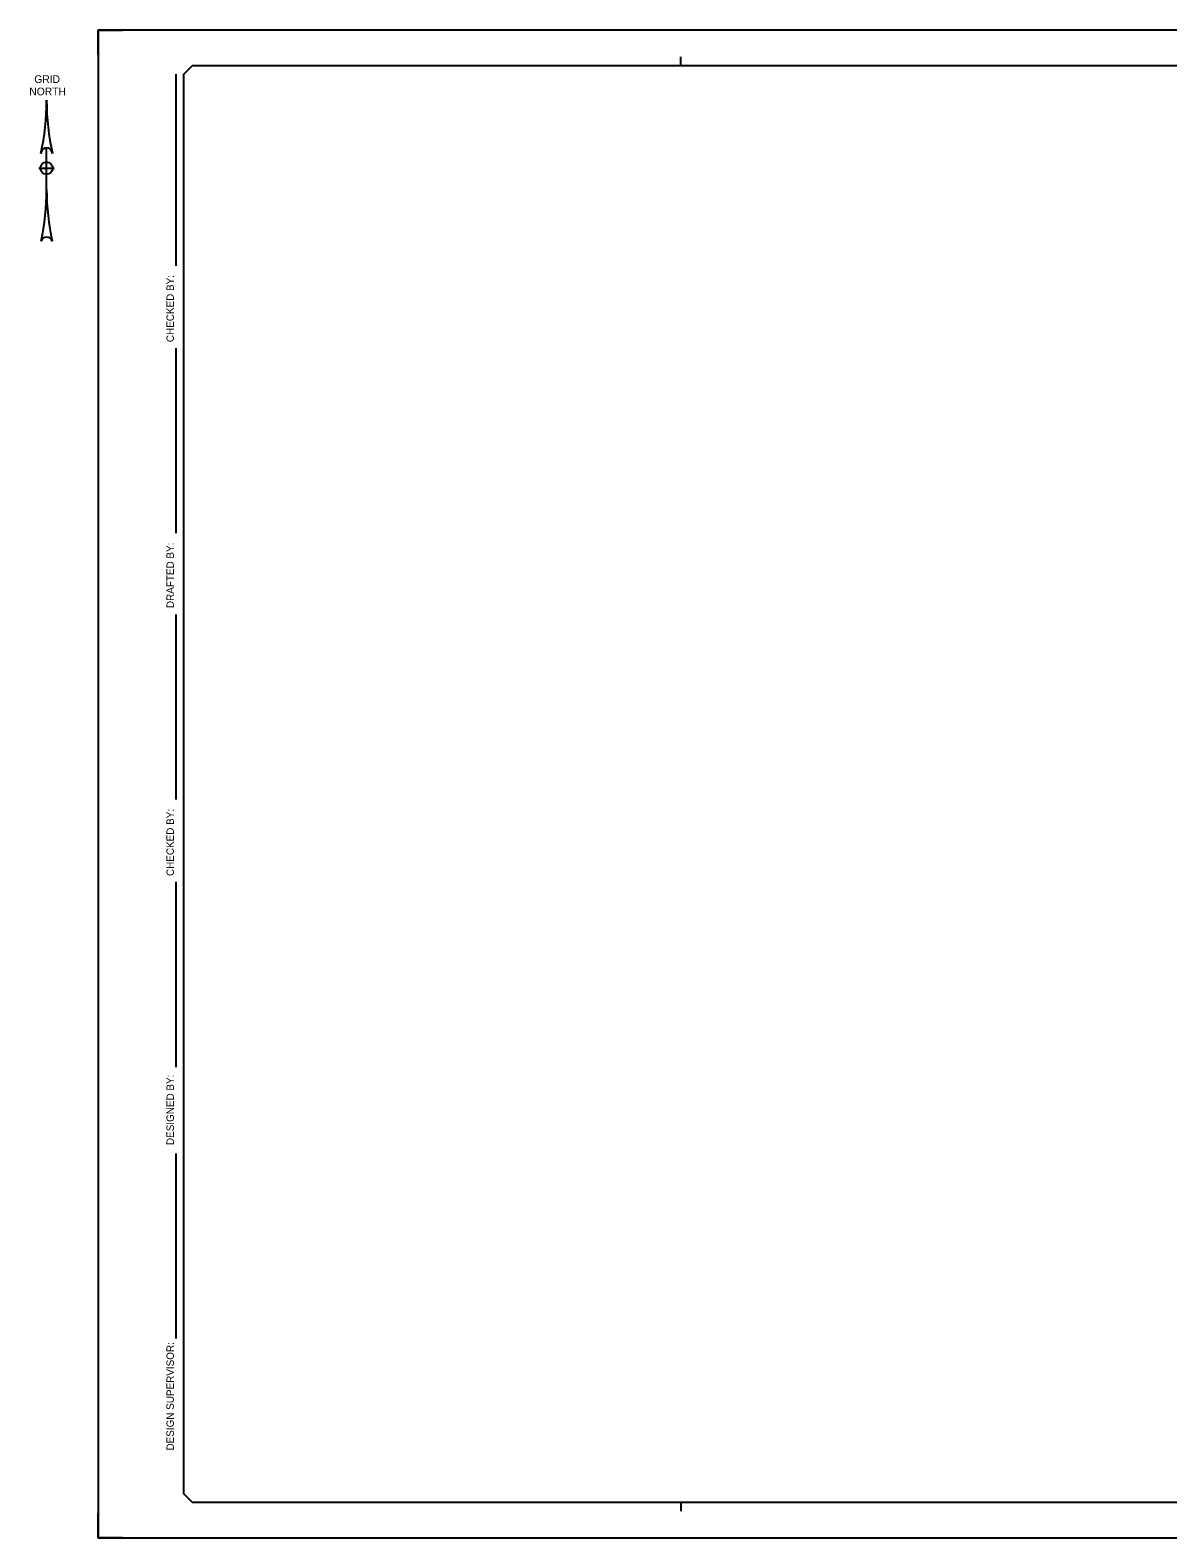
# Model space of a CAD drawing. Extents: x -0.04 to 1.42, y -0.15 to 0.92.
# Drawn here: x -0.041 to 0.65, y 0 to 0.917 of the extents above; entities that cross this region are included whole.
import ezdxf

# ---------------------------------------------------------------- set-up
doc = ezdxf.new("R2010")
doc.units = 0
for name, color, linetype in [('NNA_P', 7, 'Continuous'), ('SHEET_BORDER', 7, 'Continuous'), ('SHEET_BORDER_EDGE', 7, 'Continuous'), ('SHEET_BORDER_TEXT', 7, 'Continuous')]:
    doc.layers.add(name, color=color, linetype=linetype)

# ---------------------------------------------------------------- blocks, each defined once
blk = doc.blocks.new('NNAG')
at = {"layer": 'NNA_P'}
for p, q in [((-7.148321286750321e-19, -0.004341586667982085), (-7.148321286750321e-19, 0.004115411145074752)), ((-0.0015930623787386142, 9.10614176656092e-20), (0.0015143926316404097, 9.10614176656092e-20))]:
    blk.add_line(p, q, dxfattribs=at)
blk.add_circle((-1.5218195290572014e-05, 1.4193048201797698e-05), 0.0012394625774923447, dxfattribs=at)
for centre, radius, start, end in [((-0.04995589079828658, 0.013643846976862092), 0.04995528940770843, 347.65235, 0.11479722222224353), ((0.04995448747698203, 0.013643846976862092), 0.04995528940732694, 179.8852027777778, 192.34765000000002), ((-7.016605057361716e-07, 0.0029612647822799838), 0.001155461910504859, 0, 180), ((-0.04995598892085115, -0.004354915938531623), 0.04995528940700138, 347.8925194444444, 0.01679722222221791), ((0.04995458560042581, -0.004354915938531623), 0.049955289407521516, 179.9832027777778, 192.10748055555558), ((-1.946366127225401e-06, -0.015151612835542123), 0.0011557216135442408, 15.894822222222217, 164.1060888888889)]:
    blk.add_arc(centre, radius, start, end, dxfattribs=at)
for s, p in [('GRID', (-0.0025086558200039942, 0.017253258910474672)), ('NORTH', (-0.003516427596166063, 0.014755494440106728))]:
    blk.add_text(s, height=0.0015606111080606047, dxfattribs=at).set_placement(p)
blk = doc.blocks.new('twy_border_sheet')
at = {"layer": 'SHEET_BORDER_EDGE'}
blk.add_lwpolyline([(0, -0.3007430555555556), (0.46478472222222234, -0.3007430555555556), (0.46478472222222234, 0), (0, 0)], close=True, dxfattribs=at)
blk = doc.blocks.new('NSB_SI')
at = {"layer": 'SHEET_BORDER_EDGE'}
blk.add_blockref('twy_border_sheet', (0, 0), dxfattribs=at)

msp = doc.modelspace()

# ---------------------------------------------------------------- linework, layer by layer
at = {"layer": 'SHEET_BORDER'}
for p, q in [((0.35416666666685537, 0.8951822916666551), (0.35416666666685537, 0.9003906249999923)), ((0.047438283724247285, 0.7734739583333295), (0.047438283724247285, 0.8899739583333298)), ((0.047438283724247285, 0.610856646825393), (0.047438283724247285, 0.7234164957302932)), ((0.047438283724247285, 0.44885937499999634), (0.047438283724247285, 0.5614192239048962)), ((0.047438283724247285, 0.2862420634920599), (0.047438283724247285, 0.3988019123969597)), ((0.047438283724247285, 0.12129960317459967), (0.047438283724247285, 0.2337137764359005)), ((0.35416666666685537, 0.021484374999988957), (0.35416666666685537, 0.016276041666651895))]:
    msp.add_line(p, q, dxfattribs=at)
msp.add_lwpolyline([(1.3645833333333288, 0.02669270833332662), (1.3593749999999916, 0.021484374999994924), (0.057291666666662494, 0.021484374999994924), (0.05208333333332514, 0.02669270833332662), (0.05208333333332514, 0.8899739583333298), (0.057291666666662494, 0.8951822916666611), (1.3593749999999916, 0.8951822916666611), (1.3645833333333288, 0.8899739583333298)], close=True, dxfattribs=at)
at = {"layer": 'SHEET_BORDER_EDGE'}
for points in [[(-6.5645811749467e-15, 0.9019352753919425), (-6.5645811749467e-15, 0.9166666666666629), (0.014731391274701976, 0.9166666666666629)], [(0.014731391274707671, -6.415386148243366e-15), (-6.5645811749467e-15, -6.415386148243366e-15), (-6.5645811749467e-15, 0.014731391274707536)]]:
    msp.add_lwpolyline(points, dxfattribs=at)

# ---------------------------------------------------------------- block references
at = {"layer": 'SHEET_BORDER', "xscale": 3.0480060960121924, "yscale": 3.0480060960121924}
msp.add_blockref('NSB_SI', (-6.5645811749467e-15, 0.9166666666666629), dxfattribs=at)
at = {"layer": 'SHEET_BORDER_TEXT', "xscale": 3, "yscale": 3}
msp.add_blockref('NNAG', (-0.031365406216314, 0.8327851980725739), dxfattribs=at)

# ---------------------------------------------------------------- texts
at = {"layer": 'SHEET_BORDER_TEXT'}
for s, p in [('CHECKED BY:', (0.04598796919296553, 0.72700199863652)), ('DRAFTED BY:', (0.045987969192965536, 0.5652960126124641)), ('CHECKED BY:', (0.04598796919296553, 0.40238741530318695)), ('DESIGNED BY:', (0.04598796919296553, 0.2388175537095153)), ('DESIGN SUPERVISOR:', (0.04598796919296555, 0.05310186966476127))]:
    msp.add_text(s, height=0.0045000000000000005, rotation=89.99999999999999, dxfattribs=at).set_placement(p)

doc.saveas('drawing.dxf')
